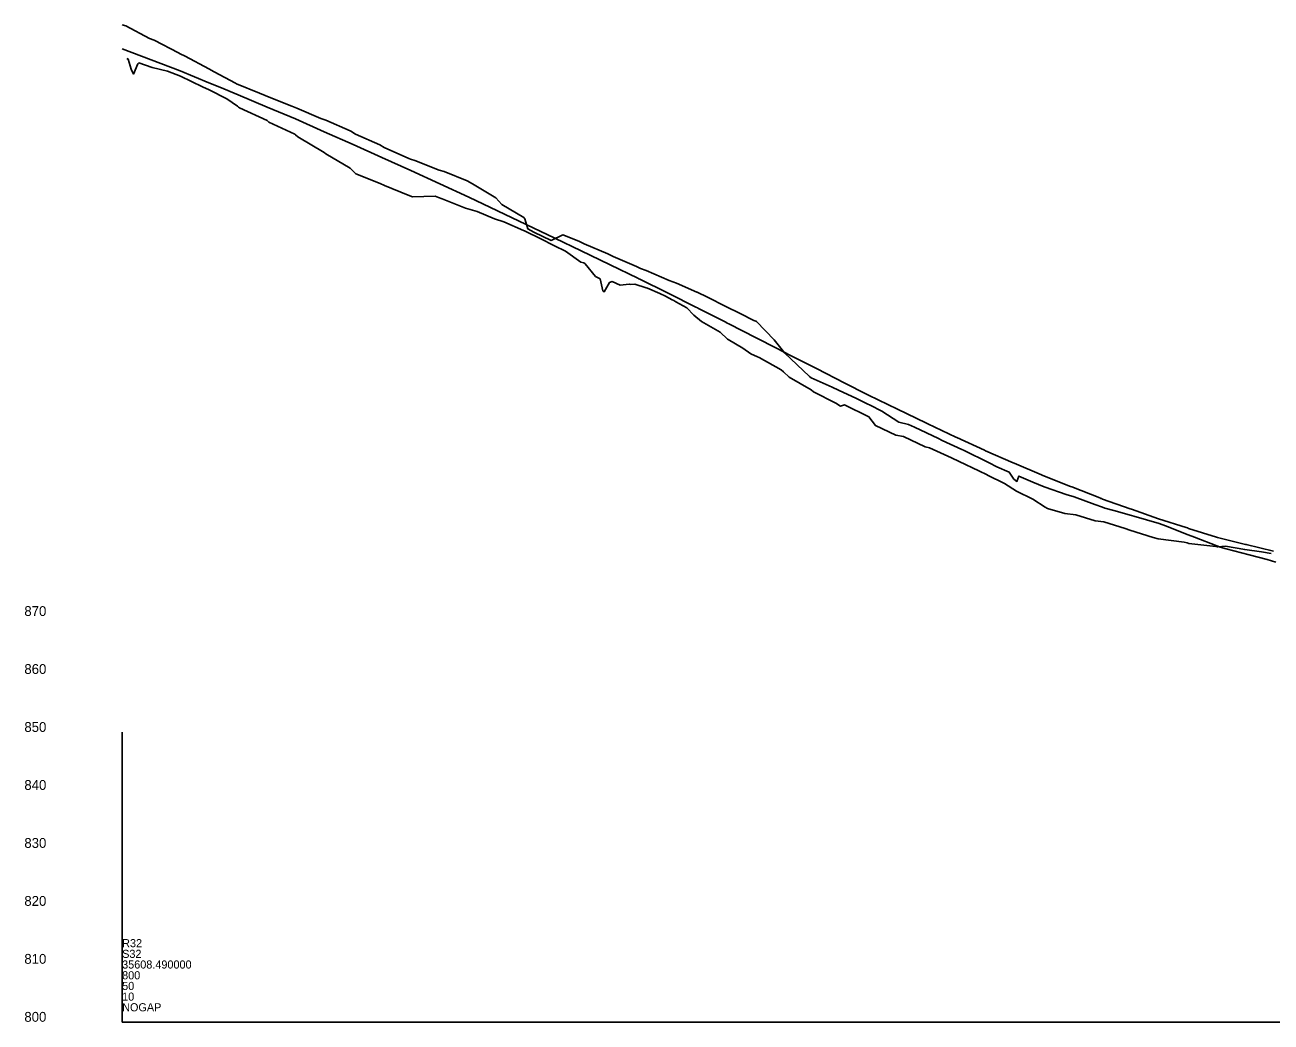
# Model space of a CAD drawing. Extents: x 1459978 to 1464152, y 1125650 to 1128602.
# Drawn here: x 1459978 to 1461053, y 1127659 to 1128519 of the extents above; entities that cross this region are included whole.
import ezdxf

# ---------------------------------------------------------------- set-up
doc = ezdxf.new("R2010")
doc.units = 0
for name, color, linetype in [('BR_EXIST_GROUND_LT', 7, 'Continuous'), ('BR_EXIST_GROUND_RT', 7, 'Continuous'), ('RD_DDB_ElevTX', 7, 'Continuous'), ('RD_DDB_Profile_EX', 7, 'Continuous'), ('RD_GPK_Profile_Cell', 7, 'Continuous')]:
    doc.layers.add(name, color=color, linetype=linetype)

msp = doc.modelspace()

# ---------------------------------------------------------------- linework, layer by layer
at = {"layer": 'BR_EXIST_GROUND_LT'}
msp.add_lwpolyline([(1460062.2, 1128519.2), (1460065.4, 1128518.3), (1460085.8, 1128507.5), (1460089.9, 1128506.2), (1460110.9, 1128495.1), (1460112.2, 1128494.4), (1460116.4, 1128492.2), (1460136.9, 1128481.2), (1460141.5, 1128478.8), (1460159.8, 1128468.9), (1460160.7, 1128468.4), (1460180.7, 1128460.3), (1460185.6, 1128458.4), (1460204.8, 1128450.6), (1460208.6, 1128449.1), (1460212.9, 1128447.4), (1460233.5, 1128438.6), (1460237.7, 1128437), (1460258.7, 1128428), (1460259.4, 1128427.7), (1460263.5, 1128425.1), (1460284.3, 1128415.9), (1460288.2, 1128413.4), (1460309.3, 1128404.1), (1460310.8, 1128403.4), (1460314.6, 1128402.4), (1460335.6, 1128393.8), (1460339.8, 1128392.8), (1460359.6, 1128384.7), (1460364.2, 1128382.2), (1460384.3, 1128370), (1460389.6, 1128364.4), (1460408.5, 1128353.1), (1460409.3, 1128352.1), (1460412, 1128343.3), (1460417.1, 1128340.4), (1460432.1, 1128333.4), (1460442.1, 1128338.3), (1460456, 1128332.7), (1460460.6, 1128330.5), (1460480.9, 1128321.7), (1460485.5, 1128319.6), (1460505.6, 1128310.8), (1460509.1, 1128309.2), (1460514, 1128307.4), (1460533.8, 1128298.7), (1460540.1, 1128296.5), (1460557.6, 1128288.8), (1460558, 1128288.7), (1460566.7, 1128284.5), (1460582.5, 1128276.4), (1460595.1, 1128270.4), (1460606.8, 1128264.4), (1460608.5, 1128263.6), (1460609, 1128263.4), (1460624.4, 1128247.5), (1460633.5, 1128236.1), (1460654.4, 1128216.3), (1460654.7, 1128215.9), (1460656.2, 1128214.9), (1460674.4, 1128206.8), (1460679.8, 1128204.1), (1460695.4, 1128196.9), (1460704.9, 1128192.2), (1460706.5, 1128191.4), (1460707, 1128191.2), (1460717.1, 1128186), (1460731.8, 1128176.5), (1460740.1, 1128174.7), (1460745.2, 1128172.2), (1460766, 1128162.4), (1460769.1, 1128160.9), (1460786.1, 1128152.9), (1460787.4, 1128152.3), (1460809.6, 1128141.4), (1460816.3, 1128138.1), (1460827, 1128133.4), (1460830.8, 1128127.5), (1460833.6, 1128125.5), (1460835.2, 1128130.1), (1460847.3, 1128124.8), (1460857, 1128120.9), (1460857.8, 1128120.5), (1460876.1, 1128114.2), (1460882.8, 1128112.3), (1460900.6, 1128105.7), (1460907.2, 1128103.2), (1460909.2, 1128102.5), (1460917.1, 1128100.5), (1460932.2, 1128096.2), (1460934.3, 1128095.5), (1460956.2, 1128089.2), (1460961.5, 1128087.2), (1460981.1, 1128079.5), (1460986.5, 1128077.5), (1461006, 1128069.8), (1461006.7, 1128069.6), (1461008.8, 1128068.8), (1461013.9, 1128067.2), (1461033.8, 1128062.1), (1461049.3, 1128058.1), (1461056.8, 1128055.8)], dxfattribs=at)
at = {"layer": 'BR_EXIST_GROUND_RT'}
msp.add_lwpolyline([(1460066.2, 1128490.2), (1460067.5, 1128489.6), (1460070, 1128481.1), (1460072, 1128476.8), (1460075.7, 1128485.7), (1460076.7, 1128486.4), (1460088.2, 1128482.6), (1460101.4, 1128479.2), (1460112.4, 1128475), (1460131.4, 1128465.7), (1460137.2, 1128463.2), (1460152.4, 1128455.5), (1460161.6, 1128449.1), (1460162.4, 1128448.3), (1460163.3, 1128447.6), (1460187.2, 1128436.9), (1460188.6, 1128435.4), (1460211.2, 1128424.9), (1460211.7, 1128424.4), (1460213.8, 1128422.6), (1460236.4, 1128409.3), (1460237.8, 1128408.1), (1460258.9, 1128395.6), (1460262.9, 1128391.6), (1460263.6, 1128390.9), (1460284.6, 1128382.5), (1460288.5, 1128380.7), (1460308.9, 1128372.5), (1460312.4, 1128370.9), (1460332.1, 1128371.6), (1460334.9, 1128370.4), (1460338.1, 1128369.2), (1460358.1, 1128361.3), (1460368.2, 1128358.3), (1460383.2, 1128351.9), (1460391.2, 1128349.5), (1460408.3, 1128341.9), (1460409.2, 1128341.6), (1460410.2, 1128341.1), (1460422.6, 1128334.9), (1460434.9, 1128328.8), (1460444.4, 1128324.1), (1460457.6, 1128314.6), (1460460.1, 1128314), (1460461.4, 1128313.1), (1460470.3, 1128302.1), (1460474.2, 1128300.1), (1460476.5, 1128290), (1460477.8, 1128289), (1460482.4, 1128297.1), (1460484.6, 1128297.8), (1460491.4, 1128294.8), (1460499.3, 1128295.7), (1460500.5, 1128295.3), (1460504.3, 1128295.6), (1460513.9, 1128292.5), (1460515, 1128292.1), (1460525.8, 1128287.6), (1460530.7, 1128285.2), (1460536.4, 1128282), (1460537.7, 1128281.6), (1460539.4, 1128280.5), (1460549, 1128275.2), (1460555, 1128269), (1460561.6, 1128263.5), (1460577.6, 1128254.2), (1460584.1, 1128248.3), (1460584.6, 1128247.9), (1460597.3, 1128240.3), (1460604.3, 1128235.5), (1460609.9, 1128233), (1460611.3, 1128232.3), (1460630.3, 1128221.6), (1460632.4, 1128220), (1460637.1, 1128215.5), (1460656.3, 1128204.5), (1460658.1, 1128202.7), (1460677.5, 1128193.1), (1460681.4, 1128190.3), (1460684.9, 1128191.6), (1460706, 1128181.2), (1460711.5, 1128173.8), (1460729.1, 1128165.4), (1460735.7, 1128164.3), (1460754.4, 1128155.3), (1460758.3, 1128154.5), (1460777.2, 1128145.8), (1460783.7, 1128142.6), (1460800.7, 1128134.7), (1460808, 1128131.1), (1460808.3, 1128131), (1460822.9, 1128123.7), (1460833.2, 1128117.2), (1460847.3, 1128110.1), (1460857.8, 1128103.4), (1460859.9, 1128102.1), (1460874.9, 1128097.8), (1460884.2, 1128096.6), (1460901, 1128091.6), (1460908.6, 1128090.6), (1460927, 1128084.8), (1460931, 1128083.3), (1460951.1, 1128077.1), (1460955.3, 1128076), (1460977.7, 1128073), (1460980.2, 1128072.4), (1460981.7, 1128072), (1461004.9, 1128069.2), (1461006.1, 1128069), (1461007.1, 1128069), (1461013.3, 1128069.7), (1461030, 1128066.7), (1461044.4, 1128064.6), (1461052.7, 1128063.2)], dxfattribs=at)
at = {"layer": 'RD_DDB_Profile_EX'}
msp.add_lwpolyline([(1460062.2, 1128498.7), (1460087.1, 1128489.1), (1460112.1, 1128479.6), (1460137, 1128469.3), (1460146.5, 1128465.4), (1460162.2, 1128458.9), (1460187.2, 1128448.4), (1460211.7, 1128438.1), (1460236.5, 1128427), (1460261.3, 1128416), (1460286.2, 1128404.9), (1460311.1, 1128393.7), (1460336.1, 1128382.1), (1460361, 1128370.6), (1460385.9, 1128358.8), (1460410.5, 1128347.1), (1460435.1, 1128335.4), (1460457.9, 1128324.5), (1460482.2, 1128312.7), (1460482.8, 1128312.4), (1460506.8, 1128300.7), (1460507.6, 1128300.3), (1460508.6, 1128299.8), (1460532.3, 1128288), (1460533.5, 1128287.5), (1460556.8, 1128275.8), (1460558.3, 1128275.1), (1460559.1, 1128274.7), (1460582.6, 1128262.7), (1460583.9, 1128262), (1460585.2, 1128261.3), (1460608.7, 1128249.3), (1460610.4, 1128248.4), (1460611.5, 1128247.8), (1460635.3, 1128235.8), (1460636.1, 1128235.3), (1460660.2, 1128223.1), (1460660.7, 1128222.8), (1460685.3, 1128210.3), (1460703.9, 1128200.8), (1460705.7, 1128199.9), (1460730.6, 1128187.8), (1460754.9, 1128175.9), (1460755.5, 1128175.6), (1460756.8, 1128175), (1460781, 1128163.7), (1460781.7, 1128163.4), (1460805.6, 1128152.3), (1460806.4, 1128151.9), (1460830.3, 1128141.6), (1460831.3, 1128141.2), (1460854.7, 1128131.1), (1460855.9, 1128130.6), (1460879.8, 1128121.1), (1460880.8, 1128120.7), (1460904.9, 1128111.2), (1460905.8, 1128110.8), (1460906.4, 1128110.6), (1460907.2, 1128110.3), (1460931.3, 1128101.8), (1460932.4, 1128101.4), (1460955.6, 1128093.3), (1460979.4, 1128085.7), (1460980.5, 1128085.3), (1460981.6, 1128085), (1461005.6, 1128077.3), (1461006.5, 1128077.1), (1461030.5, 1128071.2), (1461031.3, 1128071.1), (1461054.6, 1128065.3)], dxfattribs=at)
at = {"layer": 'RD_GPK_Profile_Cell'}
for q in [(1460062.2, 1127909.1), (1464151.9, 1127659.1), (1460062.2, 1127659.1)]:
    msp.add_line((1460062.2, 1127659.1), q, dxfattribs=at)

# ---------------------------------------------------------------- texts
at = {"layer": 'RD_DDB_ElevTX'}
for s, p in [('870', (1459977.9, 1128009.4)), ('860', (1459977.9, 1127959.4)), ('850', (1459977.9, 1127909.4)), ('840', (1459977.9, 1127859.4)), ('830', (1459977.9, 1127809.4)), ('820', (1459977.9, 1127759.4)), ('810', (1459977.9, 1127709.4)), ('800', (1459977.9, 1127659.4))]:
    msp.add_text(s, height=8.5, dxfattribs=at).set_placement(p)
at = {"layer": 'RD_GPK_Profile_Cell'}
for s, p in [('R32', (1460062.2, 1127723.7)), ('S32', (1460062.2, 1127714.5)), ('35608.490000', (1460062.2, 1127705.3)), ('800', (1460062.2, 1127696)), ('50', (1460062.2, 1127686.8)), ('10', (1460062.2, 1127677.6)), ('NOGAP', (1460062.2, 1127668.4))]:
    msp.add_text(s, height=7, dxfattribs=at).set_placement(p)

doc.saveas('drawing.dxf')
